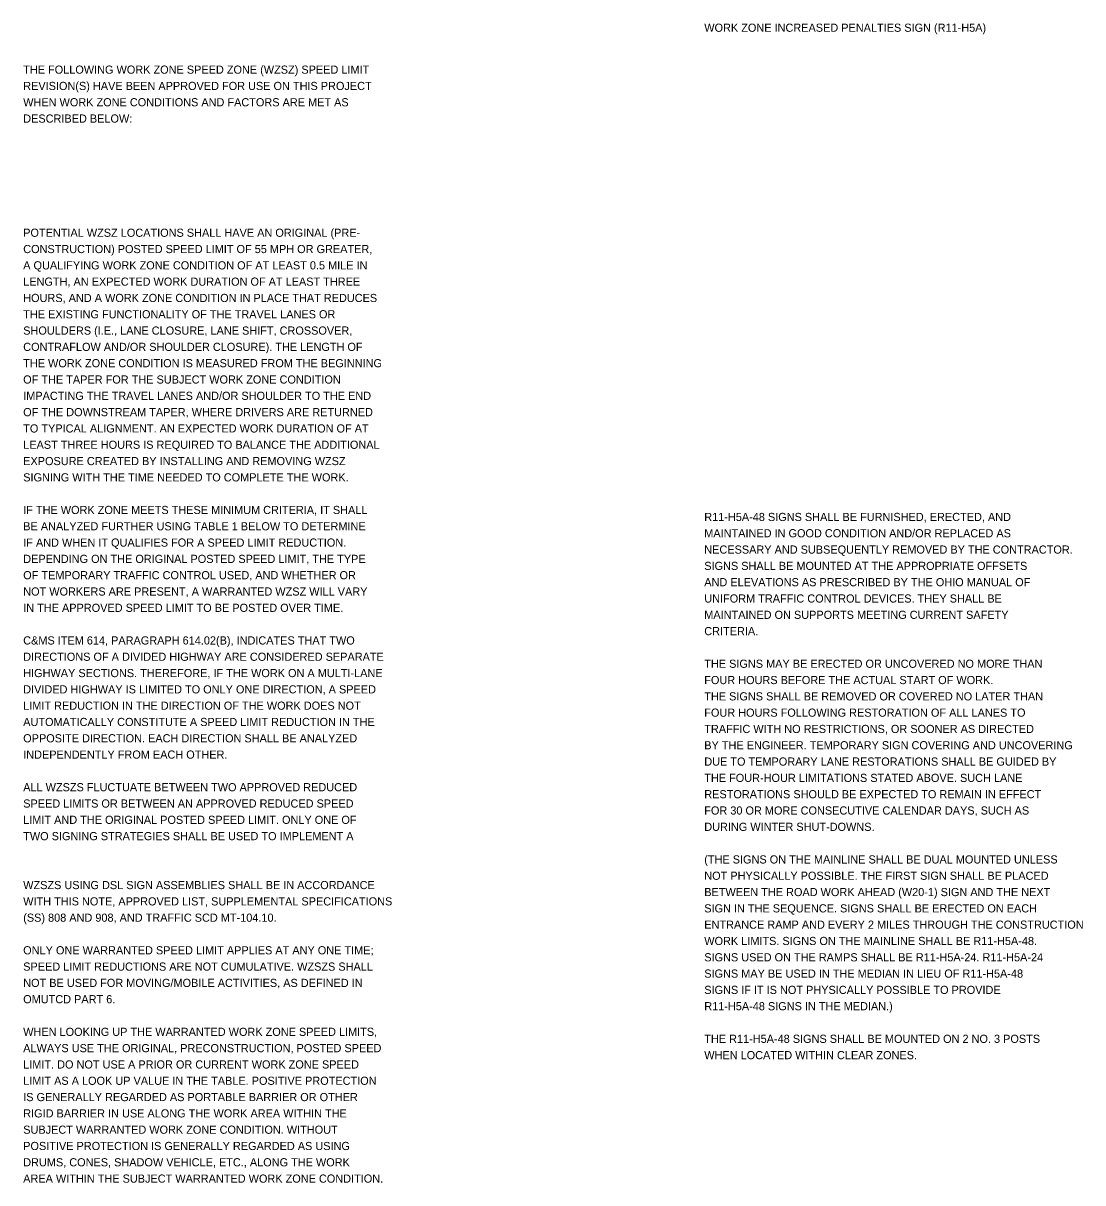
# Model space of a CAD drawing. Extents: x -19 to 34, y 0 to 22.
# Drawn here: x -18.98 to -0.79, y 1.24 to 21.15 of the extents above; entities that cross this region are included whole.
import ezdxf

# ---------------------------------------------------------------- set-up
doc = ezdxf.new("R2010")
doc.units = 0
doc.layers.add('SH_Text', color=7, linetype='Continuous')

msp = doc.modelspace()

# ---------------------------------------------------------------- texts
at = {"layer": 'SH_Text'}
for s, p in [('WORK ZONE INCREASED PENALTIES SIGN (R11-H5A)', (-7.29, 21)), ('THE FOLLOWING WORK ZONE SPEED ZONE (WZSZ) SPEED LIMIT', (-18.979, 20.28)), ('REVISION(S) HAVE BEEN APPROVED FOR USE ON THIS PROJECT', (-18.979, 20)), ('WHEN WORK ZONE CONDITIONS AND FACTORS ARE MET AS', (-18.979, 19.72)), ('DESCRIBED BELOW:', (-18.979, 19.44)), ('POTENTIAL WZSZ LOCATIONS SHALL HAVE AN ORIGINAL (PRE-', (-18.979, 17.48)), ('CONSTRUCTION) POSTED SPEED LIMIT OF 55 MPH OR GREATER,', (-18.979, 17.2)), ('A QUALIFYING WORK ZONE CONDITION OF AT LEAST 0.5 MILE IN', (-18.979, 16.92)), ('LENGTH, AN EXPECTED WORK DURATION OF AT LEAST THREE', (-18.979, 16.64)), ('HOURS, AND A WORK ZONE CONDITION IN PLACE THAT REDUCES', (-18.979, 16.36)), ('THE EXISTING FUNCTIONALITY OF THE TRAVEL LANES OR', (-18.979, 16.08)), ('SHOULDERS (I.E., LANE CLOSURE, LANE SHIFT, CROSSOVER,', (-18.979, 15.8)), ('CONTRAFLOW AND/OR SHOULDER CLOSURE). THE LENGTH OF', (-18.979, 15.52)), ('THE WORK ZONE CONDITION IS MEASURED FROM THE BEGINNING', (-18.979, 15.24)), ('OF THE TAPER FOR THE SUBJECT WORK ZONE CONDITION', (-18.979, 14.96)), ('IMPACTING THE TRAVEL LANES AND/OR SHOULDER TO THE END', (-18.979, 14.68)), ('OF THE DOWNSTREAM TAPER, WHERE DRIVERS ARE RETURNED', (-18.979, 14.4)), ('TO TYPICAL ALIGNMENT. AN EXPECTED WORK DURATION OF AT', (-18.979, 14.12)), ('LEAST THREE HOURS IS REQUIRED TO BALANCE THE ADDITIONAL', (-18.979, 13.84)), ('EXPOSURE CREATED BY INSTALLING AND REMOVING WZSZ', (-18.979, 13.56)), ('SIGNING WITH THE TIME NEEDED TO COMPLETE THE WORK.', (-18.979, 13.28)), ('IF THE WORK ZONE MEETS THESE MINIMUM CRITERIA, IT SHALL', (-18.979, 12.72)), ('BE ANALYZED FURTHER USING TABLE 1 BELOW TO DETERMINE', (-18.979, 12.44)), ('R11-H5A-48 SIGNS SHALL BE FURNISHED, ERECTED, AND', (-7.29, 12.6)), ('MAINTAINED IN GOOD CONDITION AND/OR REPLACED AS', (-7.29, 12.32)), ('IF AND WHEN IT QUALIFIES FOR A SPEED LIMIT REDUCTION.', (-18.979, 12.16)), ('NECESSARY AND SUBSEQUENTLY REMOVED BY THE CONTRACTOR.', (-7.29, 12.04)), ('DEPENDING ON THE ORIGINAL POSTED SPEED LIMIT, THE TYPE', (-18.979, 11.88)), ('SIGNS SHALL BE MOUNTED AT THE APPROPRIATE OFFSETS', (-7.29, 11.76)), ('OF TEMPORARY TRAFFIC CONTROL USED, AND WHETHER OR', (-18.979, 11.6)), ('AND ELEVATIONS AS PRESCRIBED BY THE OHIO MANUAL OF', (-7.29, 11.48)), ('NOT WORKERS ARE PRESENT, A WARRANTED WZSZ WILL VARY', (-18.979, 11.32)), ('IN THE APPROVED SPEED LIMIT TO BE POSTED OVER TIME.', (-18.979, 11.04)), ('UNIFORM TRAFFIC CONTROL DEVICES. THEY SHALL BE', (-7.29, 11.2)), ('MAINTAINED ON SUPPORTS MEETING CURRENT SAFETY', (-7.29, 10.92)), ('CRITERIA.', (-7.29, 10.64)), ('C&MS ITEM 614, PARAGRAPH 614.02(B), INDICATES THAT TWO', (-18.979, 10.48)), ('DIRECTIONS OF A DIVIDED HIGHWAY ARE CONSIDERED SEPARATE', (-18.979, 10.2)), ('THE SIGNS MAY BE ERECTED OR UNCOVERED NO MORE THAN', (-7.29, 10.08)), ('HIGHWAY SECTIONS. THEREFORE, IF THE WORK ON A MULTI-LANE', (-18.979, 9.92)), ('DIVIDED HIGHWAY IS LIMITED TO ONLY ONE DIRECTION, A SPEED', (-18.979, 9.64)), ('FOUR HOURS BEFORE THE ACTUAL START OF WORK.', (-7.29, 9.8)), ('THE SIGNS SHALL BE REMOVED OR COVERED NO LATER THAN', (-7.29, 9.52)), ('LIMIT REDUCTION IN THE DIRECTION OF THE WORK DOES NOT', (-18.979, 9.36)), ('FOUR HOURS FOLLOWING RESTORATION OF ALL LANES TO', (-7.29, 9.24)), ('AUTOMATICALLY CONSTITUTE A SPEED LIMIT REDUCTION IN THE', (-18.979, 9.08)), ('TRAFFIC WITH NO RESTRICTIONS, OR SOONER AS DIRECTED', (-7.29, 8.96)), ('OPPOSITE DIRECTION. EACH DIRECTION SHALL BE ANALYZED', (-18.979, 8.8)), ('BY THE ENGINEER. TEMPORARY SIGN COVERING AND UNCOVERING', (-7.29, 8.68)), ('INDEPENDENTLY FROM EACH OTHER.', (-18.979, 8.52)), ('DUE TO TEMPORARY LANE RESTORATIONS SHALL BE GUIDED BY', (-7.29, 8.4)), ('THE FOUR-HOUR LIMITATIONS STATED ABOVE. SUCH LANE', (-7.29, 8.12)), ('ALL WZSZS FLUCTUATE BETWEEN TWO APPROVED REDUCED', (-18.979, 7.96)), ('RESTORATIONS SHOULD BE EXPECTED TO REMAIN IN EFFECT', (-7.29, 7.84)), ('SPEED LIMITS OR BETWEEN AN APPROVED REDUCED SPEED', (-18.979, 7.68)), ('FOR 30 OR MORE CONSECUTIVE CALENDAR DAYS, SUCH AS', (-7.29, 7.56)), ('LIMIT AND THE ORIGINAL POSTED SPEED LIMIT. ONLY ONE OF', (-18.979, 7.4)), ('DURING WINTER SHUT-DOWNS.', (-7.29, 7.28)), ('TWO SIGNING STRATEGIES SHALL BE USED TO IMPLEMENT A', (-18.979, 7.12)), ('(THE SIGNS ON THE MAINLINE SHALL BE DUAL MOUNTED UNLESS', (-7.29, 6.72)), ('NOT PHYSICALLY POSSIBLE. THE FIRST SIGN SHALL BE PLACED', (-7.29, 6.44)), ('WZSZS USING DSL SIGN ASSEMBLIES SHALL BE IN ACCORDANCE', (-18.979, 6.28)), ('BETWEEN THE ROAD WORK AHEAD (W20-1) SIGN AND THE NEXT', (-7.29, 6.16)), ('WITH THIS NOTE, APPROVED LIST, SUPPLEMENTAL SPECIFICATIONS', (-18.979, 6)), ('SIGN IN THE SEQUENCE. SIGNS SHALL BE ERECTED ON EACH', (-7.29, 5.88)), ('(SS) 808 AND 908, AND TRAFFIC SCD MT-104.10.', (-18.979, 5.72)), ('ENTRANCE RAMP AND EVERY 2 MILES THROUGH THE CONSTRUCTION', (-7.29, 5.6)), ('WORK LIMITS. SIGNS ON THE MAINLINE SHALL BE R11-H5A-48.', (-7.29, 5.32)), ('ONLY ONE WARRANTED SPEED LIMIT APPLIES AT ANY ONE TIME;', (-18.979, 5.16)), ('SIGNS USED ON THE RAMPS SHALL BE R11-H5A-24. R11-H5A-24', (-7.29, 5.04)), ('SPEED LIMIT REDUCTIONS ARE NOT CUMULATIVE. WZSZS SHALL', (-18.979, 4.88)), ('SIGNS MAY BE USED IN THE MEDIAN IN LIEU OF R11-H5A-48', (-7.29, 4.76)), ('NOT BE USED FOR MOVING/MOBILE ACTIVITIES, AS DEFINED IN', (-18.979, 4.6)), ('SIGNS IF IT IS NOT PHYSICALLY POSSIBLE TO PROVIDE', (-7.29, 4.48)), ('OMUTCD PART 6.', (-18.979, 4.32)), ('R11-H5A-48 SIGNS IN THE MEDIAN.)', (-7.29, 4.2)), ('WHEN LOOKING UP THE WARRANTED WORK ZONE SPEED LIMITS,', (-18.979, 3.76)), ('ALWAYS USE THE ORIGINAL, PRECONSTRUCTION, POSTED SPEED', (-18.979, 3.48)), ('THE R11-H5A-48 SIGNS SHALL BE MOUNTED ON 2 NO. 3 POSTS', (-7.29, 3.64)), ('WHEN LOCATED WITHIN CLEAR ZONES.', (-7.29, 3.36)), ('LIMIT. DO NOT USE A PRIOR OR CURRENT WORK ZONE SPEED', (-18.979, 3.2)), ('LIMIT AS A LOOK UP VALUE IN THE TABLE. POSITIVE PROTECTION', (-18.979, 2.92)), ('IS GENERALLY REGARDED AS PORTABLE BARRIER OR OTHER', (-18.979, 2.64)), ('RIGID BARRIER IN USE ALONG THE WORK AREA WITHIN THE', (-18.979, 2.36)), ('SUBJECT WARRANTED WORK ZONE CONDITION. WITHOUT', (-18.979, 2.08)), ('POSITIVE PROTECTION IS GENERALLY REGARDED AS USING', (-18.979, 1.8)), ('DRUMS, CONES, SHADOW VEHICLE, ETC., ALONG THE WORK', (-18.979, 1.52)), ('AREA WITHIN THE SUBJECT WARRANTED WORK ZONE CONDITION.', (-18.979, 1.24))]:
    msp.add_text(s, height=0.14, dxfattribs=at).set_placement(p)

doc.saveas('drawing.dxf')
